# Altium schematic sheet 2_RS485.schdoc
size 307 x 218 mm; Symbol: Drawing-Symbol_A4; Device: Drawing-Symbol_A4; @Project Name: Temp_Con_V116; @Page Count: 2; @Update Date: 2025-01-24; @Create Date: 2025-01-22; @Schematic Name: SENS_485; @Page No: 2; @Page Name: RS485; Company: EasyEDA.com; Version: V1.0; Page Size: A4; @Create Time: 19:50:22; @Update Time: 15:45:21; Width: 1170; Height: 825; Region Start: 1; X Region Count: 6; Y Region Count: 4; Blade Width: 10; Title Block Position: 3; @Board Name: TEMP_SENS_485
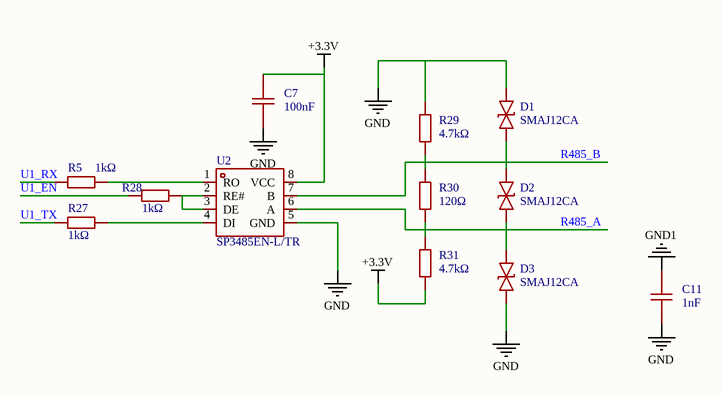
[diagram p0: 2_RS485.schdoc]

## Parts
C7  100nF  [C0805]
C11  1nF  [C0805]
D1  SMAJ12CA  [SMA_L4.4-W2.6-LS5.0-BI]
D2  SMAJ12CA  [SMA_L4.4-W2.6-LS5.0-BI]
D3  SMAJ12CA  [SMA_L4.4-W2.6-LS5.0-BI]
R5  1kΩ  [R0805]
R27  1kΩ  [R0805]
R28  1kΩ  [R0805]
R29  4.7kΩ  [R0805]
R30  120Ω  [R0805]
R31  4.7kΩ  [R0805]
U2  SP3485EN-L/TR  [SOIC-8_L5.0-W4.0-P1.27-LS6.0-BL]

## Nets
+3.3V: C7.2 R31.1 U2.8(VCC)
GND: C7.1 C11.2 D1.2 D3.1 R29.2 U2.5(GND)
GND1: C11.1
R485_A: D2.1 D3.2 R30.1 R31.2 U2.6(A)
R485_B: D1.1 D2.2 R29.1 R30.2 U2.7(B)
U1_EN: R28.1
U1_RX: R5.1
U1_TX: R27.1
NetR5_2: R5.2 U2.1(RO)
NetR27_2: R27.2 U2.4(DI)
NetR28_2: R28.2 U2.2(RE#) U2.3(DE)

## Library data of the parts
C7 = CC0805KRX7R9BB104: Manufacturer: YAGEO(国巨); Add into BOM: yes; Tolerance: ±10%; Check: true
C11 = 0805B102K102CT: Manufacturer: Walsin(华新科); Add into BOM: yes; Tolerance: ±10%
D1-D3 = SMAJ12CA_C152122: Manufacturer: BORN(伯恩半导体); Add into BOM: yes; Reverse Stand-Off Voltage (Vrwm): 12V; Maximum Clamping Voltage: 19.9V; Peak Pulse Current (Ipp): 20.1A; Breakdown Voltage: 13.3V; Type: TVS; Check: true
R5 R27 R28 = RC0805FR-071KL: Manufacturer: YAGEO(国巨); Add into BOM: yes; Tolerance: ±1%; Temperature Coefficient: ±100ppm/℃; Check: true
R29 R31 = RC0805FR-074K7L: Manufacturer: YAGEO(国巨); Add into BOM: yes; Tolerance: ±1%; Temperature Coefficient: ±100ppm/℃; Check: true
R30 = RC0805FR-07120RL: Manufacturer: YAGEO(国巨); Add into BOM: yes; Tolerance: ±1%; Temperature Coefficient: ±100ppm/℃; Check: true
U2 = SP3485EN-L/TR: Manufacturer: MaxLinear(迈凌); Add into BOM: yes; Types: Transceiver; Number of Driver: 1; Supply Voltage: 3.3V; Data Rate: 10Mbps; Check: true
